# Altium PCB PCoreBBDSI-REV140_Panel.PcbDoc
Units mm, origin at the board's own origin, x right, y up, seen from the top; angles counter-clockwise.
Board outline 146 x 110 mm, 6 copper layers (Top Layer, Int1 (GND), Int2 (Sign), Int3 (Sign), Int4 (GND), Bottom Layer), stack 1.551 mm thick; 0 components, 0 nets, 0 pads, 0 vias.
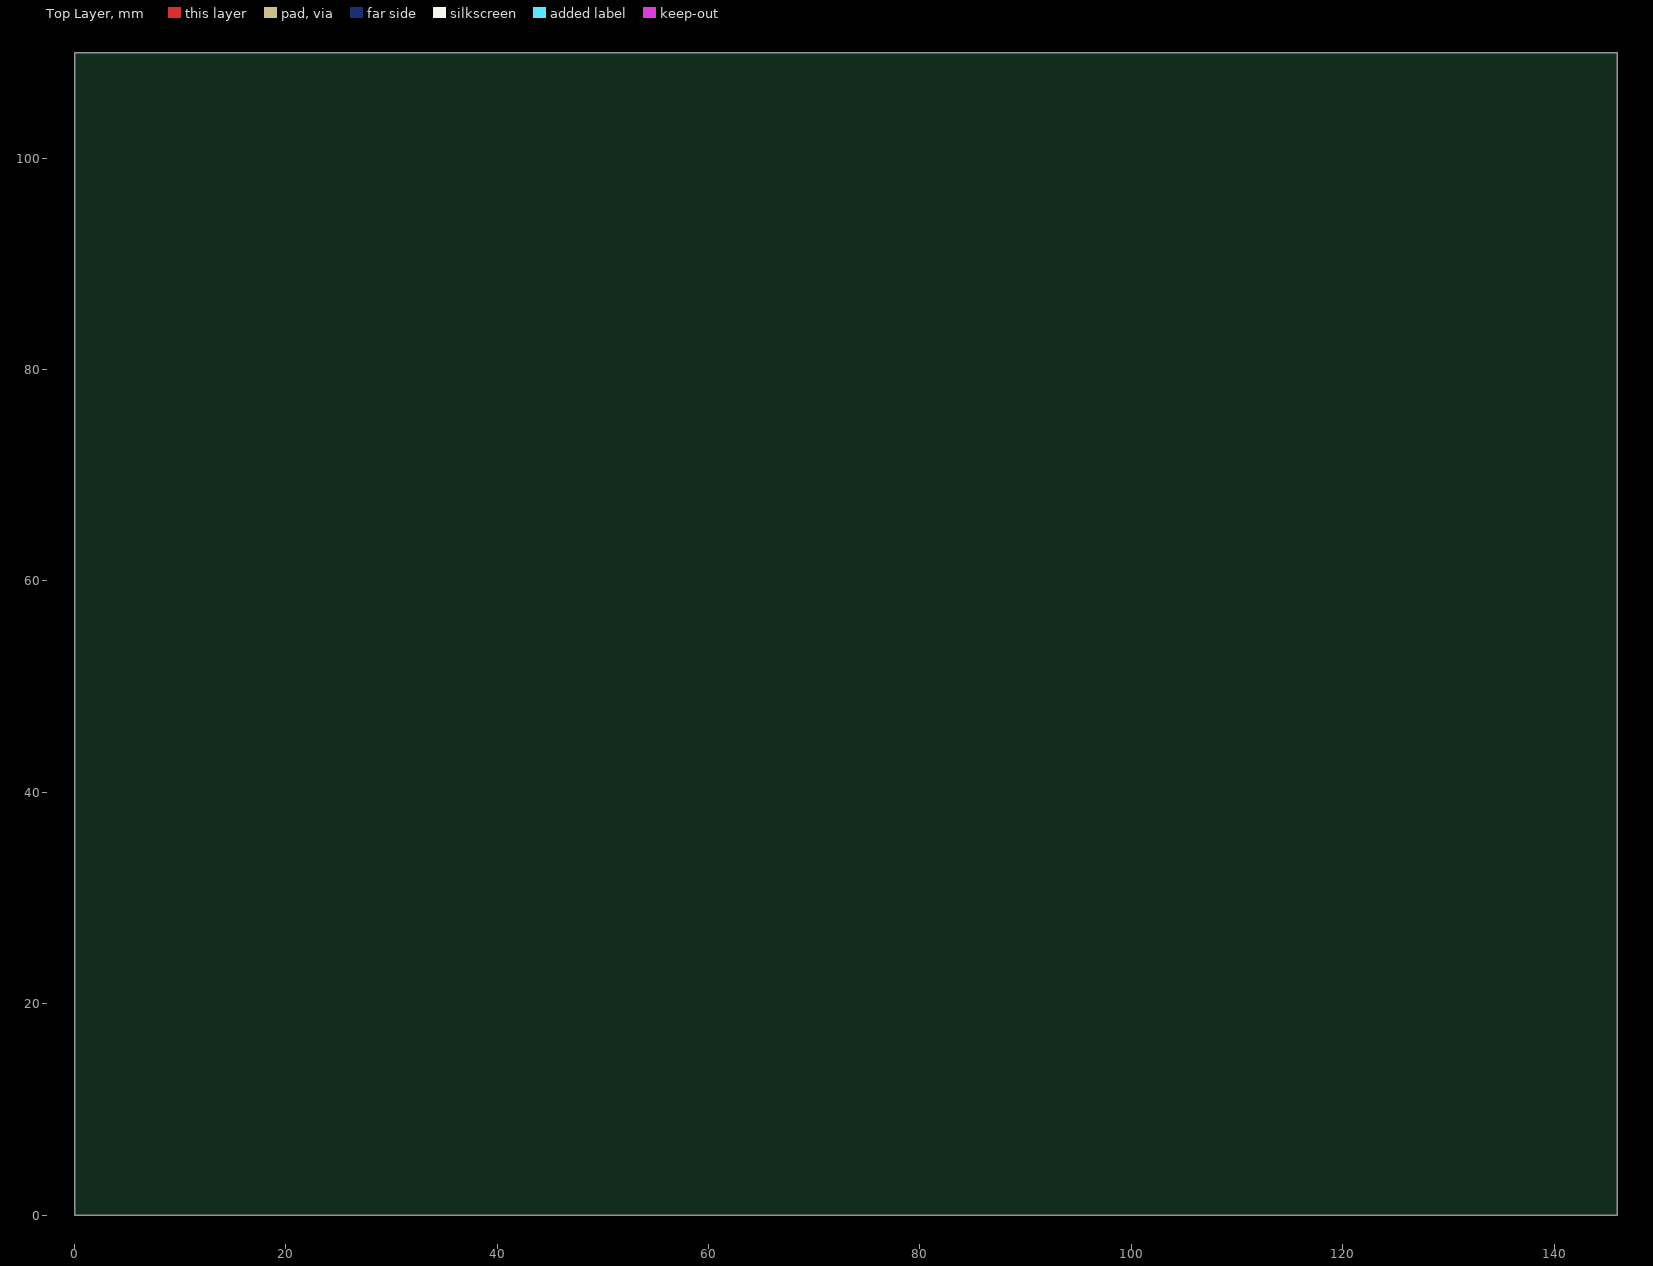
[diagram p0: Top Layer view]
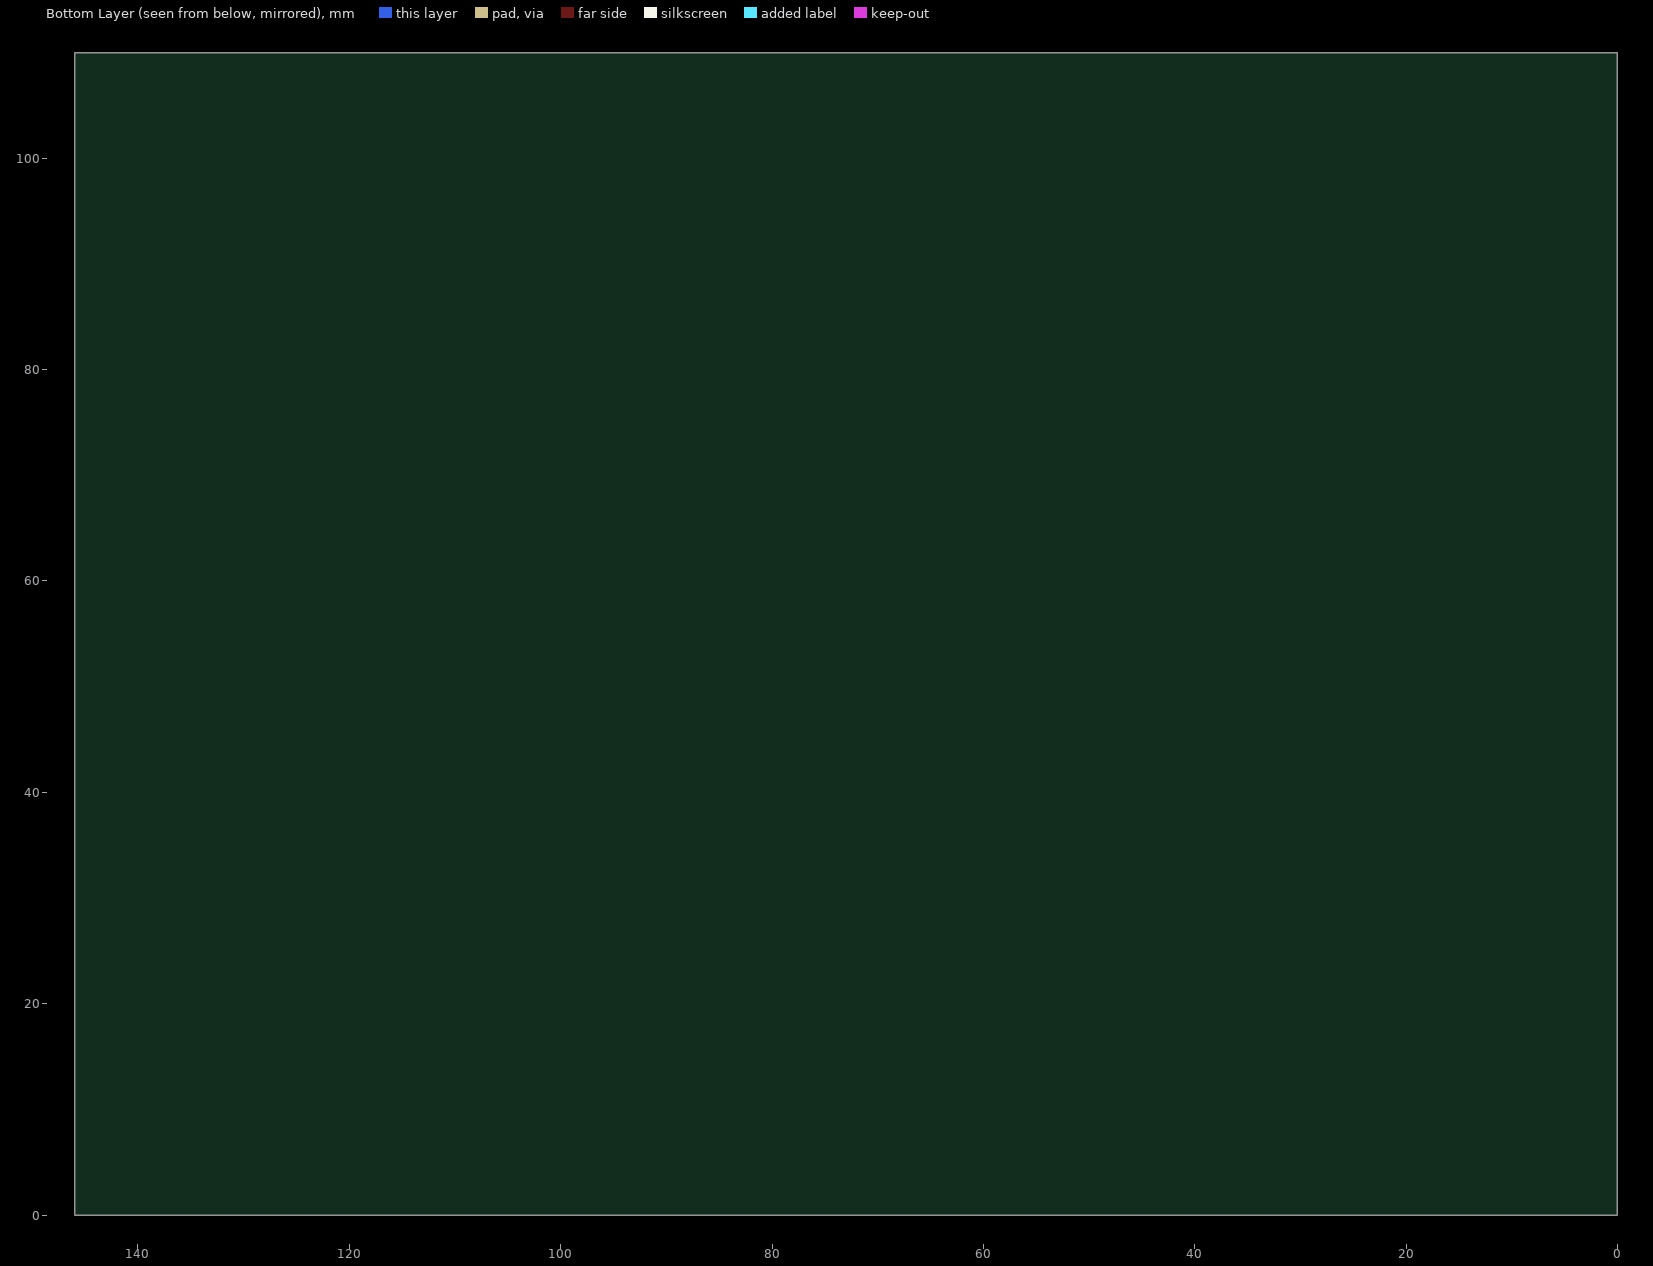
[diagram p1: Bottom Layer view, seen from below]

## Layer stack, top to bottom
Top Solder: solder mask 0.0254, SM-001, Dk 4
Top Layer: signal copper 0.035
Dielectric 1: prepreg 0.0711, PP-006, Dk 4.1
Dielectric 2: prepreg 0.0711, PP-006, Dk 4.1
Int1 (GND): signal copper 0.035
Dielectric 3: core 0.4572, Core-035, Dk 4.7
Int2 (Sign): signal copper 0.035
Dielectric 4: prepreg 0.0711, PP-006, Dk 4.1
Dielectric 5: prepreg 0.0711, PP-006, Dk 4.1
Int3 (Sign): signal copper 0.035
Dielectric 6: core 0.4572, Core-035, Dk 4.7
Int4 (GND): signal copper 0.035
Dielectric 7: prepreg 0.0711, PP-006, Dk 4.1
Dielectric 8: prepreg 0.0711, PP-006, Dk 4.1
Bottom Layer: signal copper 0.035
Bottom Solder: solder mask 0.0254, SM-001, Dk 4

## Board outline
0,0 0,110 146,110 146,0

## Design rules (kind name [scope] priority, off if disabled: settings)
Clearance [All] p1: gap=0.254 ignorepadtopadclearanceinfootprint=FALSE except(0: Arc-Hole Track-Hole SMDPad-Hole THPad-Hole Via-Hole Fill-Hole Poly-Hole Region-Hole Text-Hole)
PolygonConnect [All] p1: connectstyle=Relief reliefconductorwidth=0.254 reliefentries=4 polygonreliefangle="90 Angle" airgapwidth=0.254
RoutingVias [All] p1: holewidth=0.711 width=1.27 viastyle="Through Hole" minholewidth=0.711 minwidth=1.27 maxholewidth=0.711 maxwidth=1.27
SolderMaskExpansion [All] p1: expansion=0.102 istentingtop=FALSE
Width [All] p1: maxlimit=0.254 minlimit=0.254 preferedwidth=0.254
30 further rules are at their usual default settings.

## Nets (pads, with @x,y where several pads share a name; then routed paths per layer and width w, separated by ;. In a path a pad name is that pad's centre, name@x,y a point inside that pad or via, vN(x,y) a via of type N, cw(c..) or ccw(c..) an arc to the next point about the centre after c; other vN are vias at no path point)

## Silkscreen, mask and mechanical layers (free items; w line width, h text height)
Dimensions:
  lines w0.1: 0,0 146,0 146,110.109 0,110.109 0,0
V Cut:
  lines w0.1: 0,5 146,5 ; 0,105.029 0,105 146,105
Route Tool Path (Mech102):
  lines w2: 73,5 73,105.029

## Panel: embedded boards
"PCoreBBDSI-REV140.PcbDoc" at 74,105, 1 rows x 1 columns, spacing 63.5 x 38.1, rotation 270
"PCoreBBDSI-REV140.PcbDoc" at 72,5, 1 rows x 1 columns, spacing 63.5 x 38.1, rotation 90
